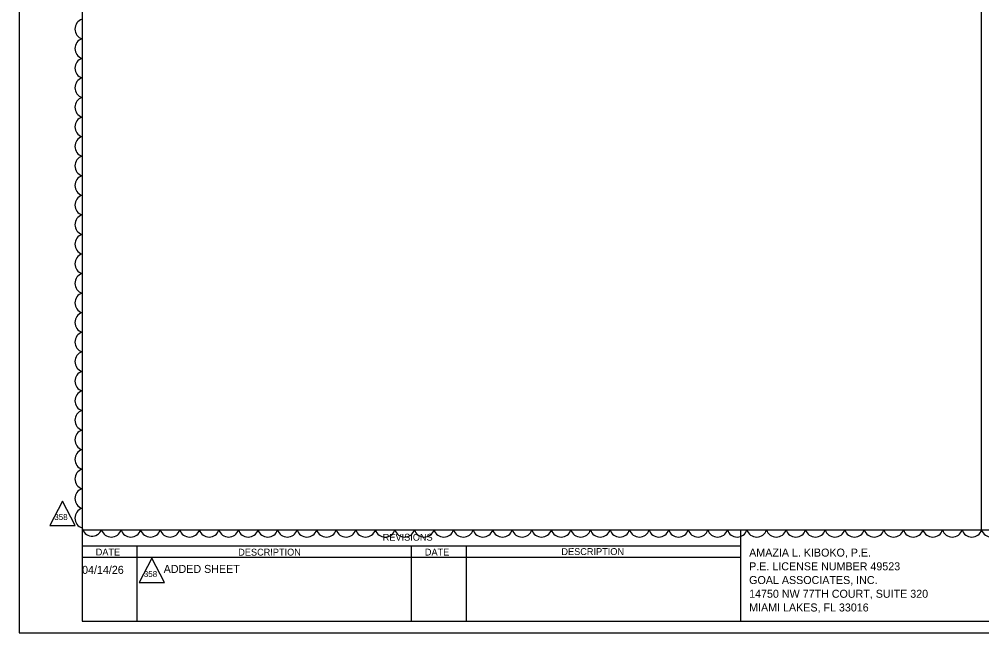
# Model space of a CAD drawing. Extents: x -816.9 to -790.1, y -2199.5 to -2188.9.
# Drawn here: x -811.34 to -802.91, y -2199.5 to -2194.13 of the extents above; entities that cross this region are included whole.
import ezdxf

# ---------------------------------------------------------------- set-up
doc = ezdxf.new("R2010")
doc.units = 0
for name, color, linetype in [('AdhocPoint_dp', 7, 'Continuous'), ('Cloud_dp', 7, 'Continuous'), ('PlotBorder_dp', 7, 'Continuous'), ('SheetBorder_dp', 7, 'Continuous'), ('SheetLines_dp', 7, 'Continuous'), ('TextLabel', 7, 'Continuous'), ('TextMisc', 7, 'Continuous'), ('TextTitle', 7, 'Continuous')]:
    doc.layers.add(name, color=color, linetype=linetype)

msp = doc.modelspace()

# ---------------------------------------------------------------- linework, layer by layer
at = {"layer": 'AdhocPoint_dp'}
msp.add_line((-811.3358, -2199.5006), (-811.3358, -2199.5006), dxfattribs=at)
at = {"layer": 'Cloud_dp'}
for points in [[(-810.9581, -2198.3492), (-811.069, -2198.5629), (-810.8472, -2198.5629)], [(-810.1749, -2198.8478), (-810.2858, -2199.0614), (-810.064, -2199.0614)]]:
    msp.add_lwpolyline(points, close=True, dxfattribs=at)
for centre, radius, start, end in [((-810.7588, -2194.2199), 0.0897, 107.5, 252.5), ((-810.7588, -2194.391), 0.0897, 107.5, 252.5), ((-810.7588, -2194.5621), 0.0897, 107.5, 252.5), ((-810.7588, -2194.7332), 0.0897, 107.5, 252.5), ((-810.7588, -2194.9044), 0.0897, 107.5, 252.5), ((-810.7588, -2195.0755), 0.0897, 107.5, 252.5), ((-810.7588, -2195.2466), 0.0897, 107.5, 252.5), ((-810.7588, -2195.4177), 0.0897, 107.5, 252.5), ((-810.7588, -2195.5889), 0.0897, 107.5, 252.5), ((-810.7588, -2195.76), 0.0897, 107.5, 252.5), ((-810.7588, -2195.9311), 0.0897, 107.5, 252.5), ((-810.7588, -2196.1022), 0.0897, 107.5, 252.5), ((-810.7588, -2196.2733), 0.0897, 107.5, 252.5), ((-810.7588, -2196.4445), 0.0897, 107.5, 252.5), ((-810.7588, -2196.6156), 0.0897, 107.5, 252.5), ((-810.7588, -2196.7867), 0.0897, 107.5, 252.5), ((-810.7588, -2196.9578), 0.0897, 107.5, 252.5), ((-810.7588, -2197.129), 0.0897, 107.5, 252.5), ((-810.7588, -2197.3001), 0.0897, 107.5, 252.5), ((-810.7588, -2197.4712), 0.0897, 107.5, 252.5), ((-810.7588, -2197.6423), 0.0897, 107.5, 252.5), ((-810.7588, -2197.8134), 0.0897, 107.5, 252.5), ((-810.7588, -2197.9846), 0.0897, 107.5, 252.5), ((-810.7588, -2198.1557), 0.0897, 107.5, 252.5), ((-810.7588, -2198.3268), 0.0897, 107.5, 252.5), ((-810.7588, -2198.4979), 0.0897, 107.5, 252.5), ((-810.698, -2198.5653), 0.0896, 191.74536, 336.74536), ((-810.5301, -2198.5737), 0.0897, 197.5, 342.5), ((-810.359, -2198.5737), 0.0897, 197.5, 342.5), ((-810.1879, -2198.5737), 0.0897, 197.5, 342.5), ((-810.0167, -2198.5737), 0.0897, 197.5, 342.5), ((-809.8456, -2198.5737), 0.0897, 197.5, 342.5), ((-809.6745, -2198.5737), 0.0897, 197.5, 342.5), ((-809.5034, -2198.5737), 0.0897, 197.5, 342.5), ((-809.3323, -2198.5737), 0.0897, 197.5, 342.5), ((-809.1611, -2198.5737), 0.0897, 197.5, 342.5), ((-808.99, -2198.5737), 0.0897, 197.5, 342.5), ((-808.8189, -2198.5737), 0.0897, 197.5, 342.5), ((-808.6478, -2198.5737), 0.0897, 197.5, 342.5), ((-808.4766, -2198.5737), 0.0897, 197.5, 342.5), ((-808.3055, -2198.5737), 0.0897, 197.5, 342.5), ((-808.1344, -2198.5737), 0.0897, 197.5, 342.5), ((-807.9633, -2198.5737), 0.0897, 197.5, 342.5), ((-807.7921, -2198.5737), 0.0897, 197.5, 342.5), ((-807.621, -2198.5737), 0.0897, 197.5, 342.5), ((-807.4499, -2198.5737), 0.0897, 197.5, 342.5), ((-807.2788, -2198.5737), 0.0897, 197.5, 342.5), ((-807.1077, -2198.5737), 0.0897, 197.5, 342.5), ((-806.9365, -2198.5737), 0.0897, 197.5, 342.5), ((-806.7654, -2198.5737), 0.0897, 197.5, 342.5), ((-806.5943, -2198.5737), 0.0897, 197.5, 342.5), ((-806.4232, -2198.5737), 0.0897, 197.5, 342.5), ((-806.252, -2198.5737), 0.0897, 197.5, 342.5), ((-806.0809, -2198.5737), 0.0897, 197.5, 342.5), ((-805.9098, -2198.5737), 0.0897, 197.5, 342.5), ((-805.7387, -2198.5737), 0.0897, 197.5, 342.5), ((-805.5676, -2198.5737), 0.0897, 197.5, 342.5), ((-805.3964, -2198.5737), 0.0897, 197.5, 342.5), ((-805.2253, -2198.5737), 0.0897, 197.5, 342.5), ((-805.0542, -2198.5737), 0.0897, 197.5, 342.5), ((-804.8831, -2198.5737), 0.0897, 197.5, 342.5), ((-804.7119, -2198.5737), 0.0897, 197.5, 342.5), ((-804.5408, -2198.5737), 0.0897, 197.5, 342.5), ((-804.3697, -2198.5737), 0.0897, 197.5, 342.5), ((-804.1986, -2198.5737), 0.0897, 197.5, 342.5), ((-804.0275, -2198.5737), 0.0897, 197.5, 342.5), ((-803.8563, -2198.5737), 0.0897, 197.5, 342.5), ((-803.6852, -2198.5737), 0.0897, 197.5, 342.5), ((-803.5141, -2198.5737), 0.0897, 197.5, 342.5), ((-803.343, -2198.5737), 0.0897, 197.5, 342.5), ((-803.1718, -2198.5737), 0.0897, 197.5, 342.5), ((-803.0007, -2198.5737), 0.0897, 197.5, 342.5), ((-802.8296, -2198.5737), 0.0897, 197.5, 342.5)]:
    msp.add_arc(centre, radius, start, end, dxfattribs=at)
at = {"layer": 'PlotBorder_dp'}
msp.add_lwpolyline([(-811.3358, -2199.5006), (-794.8358, -2199.5006), (-794.8358, -2188.9006), (-811.3358, -2188.9006)], close=True, dxfattribs=at)
at = {"layer": 'SheetBorder_dp'}
for p, q in [((-810.7858, -2189.0006), (-810.7858, -2199.4006)), ((-802.9152, -2198.6006), (-802.9152, -2189.0006)), ((-810.7858, -2198.6006), (-795.3858, -2198.6006)), ((-810.7858, -2199.4006), (-795.3858, -2199.4006))]:
    msp.add_line(p, q, dxfattribs=at)
at = {"layer": 'SheetLines_dp'}
for p, q in [((-805.0258, -2198.6006), (-805.0258, -2199.4006)), ((-810.7858, -2198.7406), (-805.0258, -2198.7406)), ((-810.3058, -2198.7406), (-810.3058, -2199.4006)), ((-807.9058, -2198.7406), (-807.9058, -2199.4006)), ((-807.4258, -2198.7406), (-807.4258, -2199.4006)), ((-810.7858, -2198.8406), (-805.0258, -2198.8406))]:
    msp.add_line(p, q, dxfattribs=at)

# ---------------------------------------------------------------- texts
at = {"layer": 'Cloud_dp'}
for p in [(-811.0294, -2198.5147), (-810.2462, -2199.0133)]:
    msp.add_text('358', height=0.0525, rotation=360, dxfattribs=at).set_placement(p)
at = {"layer": 'TextLabel'}
for s, p in [('04/14/26', (-810.7859, -2198.9855)), ('ADDED SHEET', (-810.0721, -2198.9774))]:
    msp.add_text(s, height=0.07, rotation=0, dxfattribs=at).set_placement(p)
at = {"layer": 'TextMisc'}
msp.add_text('REVISIONS', height=0.06, dxfattribs=at).set_placement((-808.1553, -2198.6955))
for s, rotation, p in [('DATE', 359.86925, (-810.6668, -2198.8247)), ('DESCRIPTION', 0.04975, (-809.4198, -2198.8259)), ('DATE', 359.86925, (-807.7868, -2198.8253)), ('DESCRIPTION', 0.04975, (-806.5922, -2198.8209))]:
    msp.add_text(s, height=0.06, rotation=rotation, dxfattribs=at).set_placement(p)
at = {"layer": 'TextTitle'}
for s, p in [('AMAZIA L. KIBOKO, P.E.', (-804.9493, -2198.8346)), ('P.E. LICENSE NUMBER 49523', (-804.9493, -2198.9546)), ('GOAL ASSOCIATES, INC.', (-804.9493, -2199.0746)), ('14750 NW 77TH COURT, SUITE 320', (-804.9493, -2199.1946)), ('MIAMI LAKES, FL 33016', (-804.9493, -2199.3146))]:
    msp.add_text(s, height=0.07, dxfattribs=at).set_placement(p)

doc.saveas('drawing.dxf')
